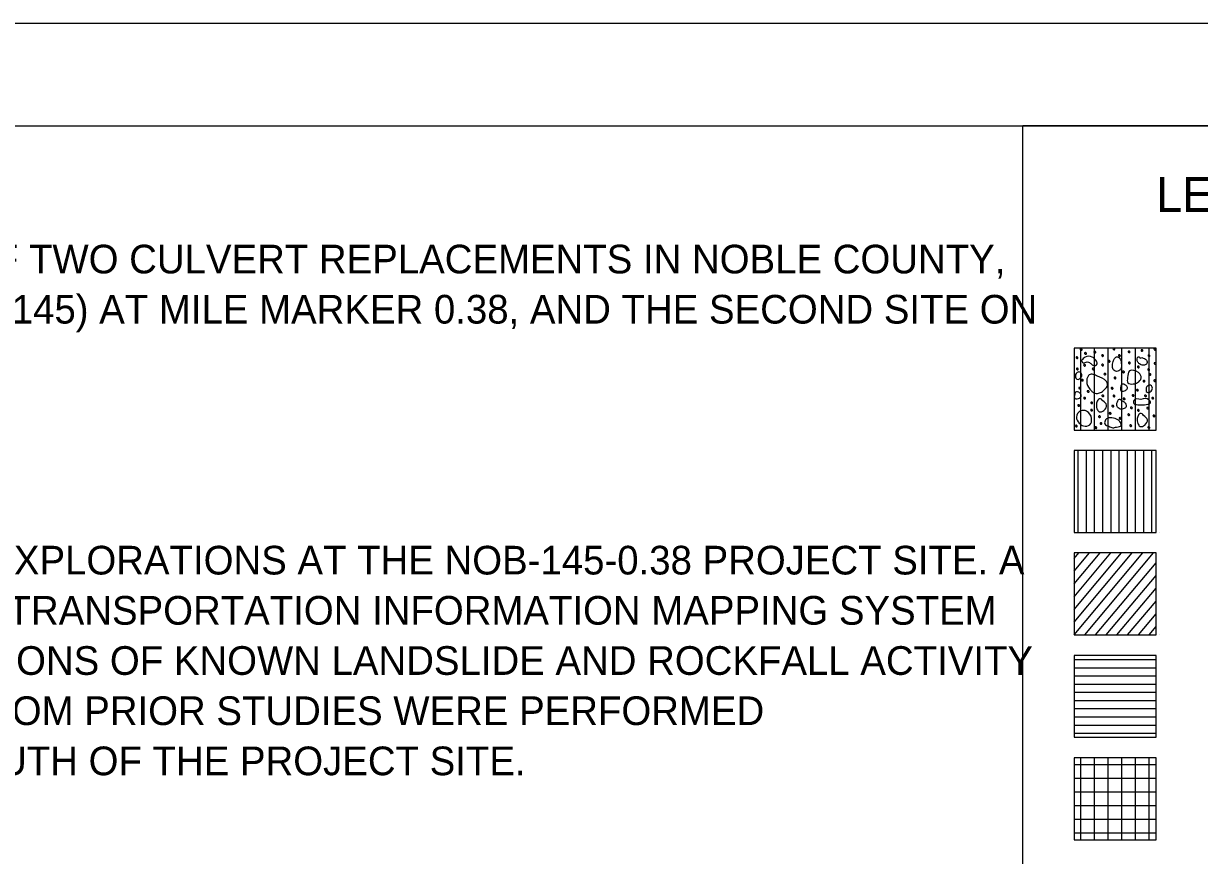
# Model space of a CAD drawing. Extents: x 0 to 34, y -8.9 to 22.
# Drawn here: x 6.83 to 12.57, y 17.94 to 22 of the extents above; entities that cross this region are included whole.
import ezdxf

# ---------------------------------------------------------------- set-up
doc = ezdxf.new("R2010")
doc.units = 0
for name, color, linetype in [('Default', 7, 'Continuous'), ('SH_Border', 7, 'Continuous'), ('SH_Cut_Line', 7, 'Continuous'), ('SH_Data', 7, 'Continuous'), ('SH_Text', 7, 'Continuous')]:
    doc.layers.add(name, color=color, linetype=linetype)

msp = doc.modelspace()

# ---------------------------------------------------------------- linework, layer by layer
at = {"layer": 'Default'}
for p, q in [((11.9545, 20.415), (11.9545, 20.415)), ((11.9878, 20.015), (11.9878, 20.415)), ((12.0545, 20.015), (12.0545, 20.415)), ((12.1212, 20.015), (12.1212, 20.415)), ((12.1878, 20.015), (12.1878, 20.415)), ((12.2545, 20.015), (12.2545, 20.415)), ((12.3212, 20.015), (12.3212, 20.415)), ((12.3545, 20.415), (12.3545, 20.415)), ((11.9545, 20.015), (11.9545, 20.015)), ((12.3545, 20.015), (12.3545, 20.015)), ((11.9545, 19.915), (11.9545, 19.915)), ((11.9745, 19.515), (11.9745, 19.915)), ((12.0145, 19.515), (12.0145, 19.915)), ((12.0545, 19.515), (12.0545, 19.915)), ((12.0945, 19.515), (12.0945, 19.915)), ((12.1345, 19.515), (12.1345, 19.915)), ((12.1745, 19.515), (12.1745, 19.915)), ((12.2145, 19.515), (12.2145, 19.915)), ((12.2545, 19.515), (12.2545, 19.915)), ((12.2945, 19.515), (12.2945, 19.915)), ((12.3345, 19.515), (12.3345, 19.915)), ((12.3545, 19.915), (12.3545, 19.915)), ((11.9545, 19.515), (11.9545, 19.515)), ((11.9545, 19.5128), (11.9545, 19.5128)), ((12.3545, 19.515), (12.3545, 19.515)), ((12.3723, 19.5128), (12.3723, 19.5128)), ((11.9544, 19.3259), (12.0292, 19.415)), ((11.9544, 19.2637), (12.0814, 19.415)), ((11.9544, 19.2015), (12.1336, 19.415)), ((11.9544, 19.1393), (12.1858, 19.415)), ((11.9544, 19.077), (12.2381, 19.415)), ((11.9545, 19.015), (12.2903, 19.415)), ((11.9545, 19.3883), (11.9769, 19.415)), ((12.0068, 19.015), (12.3425, 19.415)), ((12.059, 19.015), (12.3545, 19.3671)), ((12.1112, 19.015), (12.3545, 19.3049)), ((12.1634, 19.015), (12.3545, 19.2427)), ((12.2157, 19.015), (12.3545, 19.1805)), ((12.2679, 19.015), (12.3545, 19.1182)), ((12.3201, 19.015), (12.3545, 19.056)), ((11.9545, 19.015), (11.9545, 19.015)), ((12.3722, 19.015), (12.3722, 19.015)), ((11.9545, 18.915), (11.9545, 18.915)), ((11.9545, 18.895), (12.3545, 18.895)), ((12.3545, 18.915), (12.3545, 18.915)), ((11.9545, 18.855), (12.3545, 18.855)), ((11.9545, 18.815), (12.3545, 18.815)), ((11.9545, 18.775), (12.3545, 18.775)), ((11.9545, 18.735), (12.3545, 18.735)), ((11.9545, 18.695), (12.3545, 18.695)), ((11.9545, 18.655), (12.3545, 18.655)), ((11.9545, 18.615), (12.3545, 18.615)), ((11.9545, 18.575), (12.3545, 18.575)), ((11.9545, 18.535), (12.3545, 18.535)), ((11.9545, 18.515), (11.9545, 18.515)), ((12.3545, 18.515), (12.3545, 18.515)), ((11.9545, 18.415), (11.9545, 18.415)), ((11.9545, 18.3816), (12.3545, 18.3816)), ((11.9879, 18.015), (11.9879, 18.415)), ((12.0546, 18.015), (12.0546, 18.415)), ((12.1212, 18.015), (12.1212, 18.415)), ((12.1879, 18.015), (12.1879, 18.415)), ((12.2546, 18.015), (12.2546, 18.415)), ((12.3212, 18.015), (12.3212, 18.415)), ((12.3545, 18.415), (12.3545, 18.415)), ((11.9545, 18.315), (12.3545, 18.315)), ((11.9545, 18.2483), (12.3545, 18.2483)), ((11.9545, 18.1816), (12.3545, 18.1816)), ((11.9545, 18.115), (12.3545, 18.115)), ((11.9545, 18.0483), (12.3545, 18.0483)), ((11.9545, 18.015), (11.9545, 18.015)), ((12.3545, 18.015), (12.3545, 18.015))]:
    msp.add_line(p, q, dxfattribs=at)
for points in [[(11.9723, 20.3702), (11.9731, 20.3683), (11.9719, 20.3658), (11.9693, 20.3648), (11.9667, 20.3656), (11.9647, 20.3674), (11.9639, 20.3694), (11.9654, 20.3722), (11.9679, 20.3724), (11.9699, 20.3723), (11.9723, 20.3702)], [(11.9924, 20.4103), (11.9934, 20.4083), (11.9922, 20.4059), (11.9894, 20.4047), (11.9869, 20.4056), (11.9849, 20.4074), (11.984, 20.4094), (11.9856, 20.4122), (11.988, 20.4124), (11.99, 20.4123), (11.9924, 20.4103)], [(11.9913, 20.3546), (12.0083, 20.3716), (12.0423, 20.3716), (12.0601, 20.3562), (12.0675, 20.3383), (12.0593, 20.3302), (12.0423, 20.3343), (12.0294, 20.3448), (12.018, 20.3481), (11.9994, 20.344), (11.993, 20.3481), (11.9913, 20.3546)], [(12.0138, 20.3907), (12.0147, 20.3888), (12.0136, 20.3864), (12.0108, 20.3852), (12.0083, 20.3861), (12.0063, 20.388), (12.0054, 20.39), (12.007, 20.3927), (12.0094, 20.393), (12.0114, 20.3928), (12.0138, 20.3907)], [(12.0596, 20.3973), (12.0606, 20.3953), (12.0594, 20.3929), (12.0566, 20.3917), (12.0541, 20.3926), (12.0521, 20.3945), (12.0512, 20.3965), (12.0528, 20.3992), (12.0552, 20.3995), (12.0572, 20.3993), (12.0596, 20.3973)], [(12.0974, 20.3803), (12.0982, 20.3784), (12.097, 20.3759), (12.0944, 20.3748), (12.0918, 20.3757), (12.0898, 20.3775), (12.0889, 20.3795), (12.0905, 20.3823), (12.0929, 20.3825), (12.0949, 20.3824), (12.0974, 20.3803)], [(12.147, 20.3553), (12.1412, 20.3302), (12.1458, 20.3107), (12.1618, 20.3015), (12.1813, 20.3107), (12.1847, 20.3416), (12.1767, 20.3657), (12.1618, 20.3726), (12.1492, 20.3611), (12.147, 20.3553)], [(12.1526, 20.4124), (12.1534, 20.4105), (12.1523, 20.4081), (12.1496, 20.407), (12.147, 20.4078), (12.145, 20.4097), (12.1442, 20.4117), (12.1457, 20.4144), (12.1482, 20.4147), (12.1502, 20.4146), (12.1526, 20.4124)], [(12.1795, 20.3799), (12.1805, 20.378), (12.1793, 20.3756), (12.1765, 20.3744), (12.174, 20.3753), (12.172, 20.3772), (12.1711, 20.3792), (12.1727, 20.3819), (12.1751, 20.3822), (12.1771, 20.382), (12.1795, 20.3799)], [(12.2265, 20.3985), (12.2274, 20.3965), (12.2263, 20.3941), (12.2235, 20.393), (12.221, 20.3939), (12.219, 20.3957), (12.2181, 20.3977), (12.2196, 20.4005), (12.2221, 20.4007), (12.2241, 20.4005), (12.2265, 20.3985)], [(12.2632, 20.3687), (12.2638, 20.3492), (12.274, 20.3377), (12.2912, 20.332), (12.305, 20.3348), (12.3107, 20.3486), (12.3027, 20.3612), (12.2912, 20.3669), (12.2844, 20.3687), (12.278, 20.3663), (12.273, 20.3715), (12.2666, 20.3721), (12.2632, 20.3687)], [(12.2894, 20.4047), (12.2902, 20.4029), (12.289, 20.4005), (12.2864, 20.3993), (12.2838, 20.4001), (12.2818, 20.402), (12.2809, 20.404), (12.2824, 20.4067), (12.2849, 20.407), (12.2869, 20.4069), (12.2894, 20.4047)], [(12.3237, 20.3799), (12.3245, 20.378), (12.3235, 20.3756), (12.3207, 20.3744), (12.3181, 20.3753), (12.3161, 20.3772), (12.3153, 20.3792), (12.3169, 20.3819), (12.3193, 20.3822), (12.3213, 20.382), (12.3237, 20.3799)], [(12.3527, 20.4104), (12.3536, 20.4085), (12.3524, 20.4061), (12.3497, 20.405), (12.3471, 20.4058), (12.3451, 20.4077), (12.3443, 20.4097), (12.3458, 20.4124), (12.3483, 20.4127), (12.3503, 20.4125), (12.3527, 20.4104)], [(11.9739, 20.3151), (11.9747, 20.3132), (11.9736, 20.3107), (11.9709, 20.3096), (11.9683, 20.3105), (11.9663, 20.3123), (11.9655, 20.3143), (11.967, 20.3171), (11.9695, 20.3173), (11.9715, 20.3172), (11.9739, 20.3151)], [(12.0094, 20.333), (12.0104, 20.331), (12.0092, 20.3286), (12.0065, 20.3274), (12.004, 20.3283), (12.002, 20.3302), (12.001, 20.3322), (12.0026, 20.3349), (12.005, 20.3352), (12.0071, 20.335), (12.0094, 20.333)], [(12.0516, 20.3151), (12.0525, 20.3132), (12.0514, 20.3107), (12.0486, 20.3096), (12.046, 20.3105), (12.044, 20.3123), (12.0432, 20.3143), (12.0448, 20.3171), (12.0472, 20.3173), (12.0492, 20.3172), (12.0516, 20.3151)], [(12.0973, 20.334), (12.0981, 20.3322), (12.097, 20.3297), (12.0943, 20.3286), (12.0917, 20.3294), (12.0897, 20.3313), (12.0888, 20.3333), (12.0904, 20.336), (12.0928, 20.3363), (12.0949, 20.3362), (12.0973, 20.334)], [(12.1294, 20.3523), (12.1302, 20.3505), (12.129, 20.348), (12.1264, 20.3469), (12.1238, 20.3477), (12.1218, 20.3496), (12.1209, 20.3516), (12.1225, 20.3543), (12.125, 20.3546), (12.127, 20.3545), (12.1294, 20.3523)], [(12.2281, 20.3442), (12.229, 20.3423), (12.2279, 20.3399), (12.2251, 20.3388), (12.2225, 20.3397), (12.2205, 20.3415), (12.2197, 20.3435), (12.2213, 20.3462), (12.2237, 20.3465), (12.2257, 20.3464), (12.2281, 20.3442)], [(12.2719, 20.3247), (12.2727, 20.3229), (12.2716, 20.3205), (12.2689, 20.3193), (12.2663, 20.3202), (12.2643, 20.3221), (12.2635, 20.3241), (12.265, 20.3268), (12.2675, 20.3271), (12.2695, 20.3269), (12.2719, 20.3247)], [(12.3221, 20.3118), (12.323, 20.3099), (12.3218, 20.3075), (12.319, 20.3064), (12.3165, 20.3072), (12.3145, 20.3091), (12.3136, 20.3111), (12.3152, 20.3138), (12.3176, 20.3141), (12.3196, 20.314), (12.3221, 20.3118)], [(12.3535, 20.3419), (12.3543, 20.3401), (12.3531, 20.3376), (12.3505, 20.3365), (12.3479, 20.3373), (12.3459, 20.3391), (12.345, 20.3411), (12.3466, 20.3439), (12.349, 20.3441), (12.3511, 20.3441), (12.3535, 20.3419)], [(11.97, 20.2957), (11.978, 20.2997), (11.9878, 20.2951), (11.9924, 20.2842), (11.989, 20.2738), (11.9815, 20.2658), (11.9735, 20.2624), (11.9626, 20.2688), (11.9615, 20.2784), (11.962, 20.2865), (11.97, 20.2957)], [(11.9982, 20.2604), (11.999, 20.2586), (11.9979, 20.2561), (11.9952, 20.255), (11.9926, 20.2558), (11.9906, 20.2577), (11.9897, 20.2597), (11.9913, 20.2624), (11.9938, 20.2627), (11.9958, 20.2626), (11.9982, 20.2604)], [(12.0386, 20.2065), (12.0169, 20.2432), (12.0192, 20.2718), (12.0284, 20.2845), (12.0478, 20.2867), (12.0685, 20.2776), (12.112, 20.2523), (12.1165, 20.2283), (12.1085, 20.2192), (12.0925, 20.2031), (12.0741, 20.1951), (12.0627, 20.1939), (12.0501, 20.1973), (12.0386, 20.2065)], [(12.1085, 20.2893), (12.1094, 20.2875), (12.1082, 20.2851), (12.1055, 20.2839), (12.1029, 20.2847), (12.1009, 20.2867), (12.1, 20.2887), (12.1016, 20.2913), (12.104, 20.2917), (12.106, 20.2915), (12.1085, 20.2893)], [(12.158, 20.2712), (12.159, 20.2692), (12.158, 20.2668), (12.1552, 20.2657), (12.1526, 20.2665), (12.1506, 20.2684), (12.1498, 20.2704), (12.1514, 20.2731), (12.1538, 20.2734), (12.1558, 20.2733), (12.158, 20.2712)], [(12.199, 20.3005), (12.1999, 20.2986), (12.1987, 20.2962), (12.196, 20.295), (12.1935, 20.2959), (12.1914, 20.2978), (12.1905, 20.2997), (12.1921, 20.3025), (12.1945, 20.3027), (12.1965, 20.3026), (12.199, 20.3005)], [(12.2153, 20.2711), (12.225, 20.3035), (12.2687, 20.2954), (12.2816, 20.2695), (12.2639, 20.2467), (12.2428, 20.2403), (12.2169, 20.2452), (12.2153, 20.2711)], [(12.2995, 20.2551), (12.3003, 20.2532), (12.2991, 20.2508), (12.2964, 20.2497), (12.2938, 20.2505), (12.2918, 20.2523), (12.291, 20.2543), (12.2925, 20.2571), (12.295, 20.2574), (12.297, 20.2572), (12.2995, 20.2551)], [(12.3285, 20.2875), (12.3295, 20.2857), (12.3283, 20.2832), (12.3255, 20.2821), (12.323, 20.2829), (12.321, 20.2847), (12.3201, 20.2867), (12.3217, 20.2895), (12.3241, 20.2898), (12.3261, 20.2897), (12.3285, 20.2875)], [(12.352, 20.2574), (12.353, 20.2556), (12.3518, 20.2531), (12.349, 20.252), (12.3465, 20.2528), (12.3445, 20.2546), (12.3436, 20.2566), (12.3452, 20.2594), (12.3476, 20.2597), (12.3496, 20.2596), (12.352, 20.2574)], [(11.957, 20.1852), (11.961, 20.1998), (11.9829, 20.1958), (11.9893, 20.1828), (11.9804, 20.1715), (11.9699, 20.1683), (11.957, 20.1707), (11.957, 20.1852)], [(11.9858, 20.2213), (11.9867, 20.2194), (11.9855, 20.217), (11.9828, 20.2159), (11.9802, 20.2167), (11.9782, 20.2186), (11.9774, 20.2206), (11.979, 20.2233), (11.9814, 20.2236), (11.9834, 20.2235), (11.9858, 20.2213)], [(12.0269, 20.2052), (12.0279, 20.2033), (12.0267, 20.2008), (12.024, 20.1997), (12.0215, 20.2005), (12.0195, 20.2024), (12.0186, 20.2044), (12.0201, 20.2071), (12.0226, 20.2074), (12.0246, 20.2072), (12.0269, 20.2052)], [(12.144, 20.2203), (12.1448, 20.2185), (12.1436, 20.2161), (12.141, 20.2149), (12.1384, 20.2157), (12.1364, 20.2177), (12.1355, 20.2197), (12.137, 20.2223), (12.1395, 20.2227), (12.1415, 20.2225), (12.144, 20.2203)], [(12.1816, 20.2208), (12.1865, 20.2371), (12.2083, 20.233), (12.2148, 20.22), (12.2059, 20.2087), (12.1954, 20.2054), (12.1824, 20.2079), (12.1816, 20.2208)], [(12.267, 20.2113), (12.2679, 20.2095), (12.2667, 20.207), (12.264, 20.2059), (12.2615, 20.2067), (12.2595, 20.2086), (12.2585, 20.2106), (12.2601, 20.2133), (12.2626, 20.2136), (12.2646, 20.2135), (12.267, 20.2113)], [(12.3149, 20.2316), (12.3224, 20.235), (12.332, 20.2304), (12.3366, 20.2195), (12.3332, 20.2092), (12.3258, 20.2012), (12.3178, 20.1977), (12.3069, 20.2041), (12.3057, 20.2138), (12.3063, 20.2218), (12.3149, 20.2316)], [(12.0094, 20.1726), (12.0104, 20.1706), (12.0092, 20.1682), (12.0065, 20.167), (12.004, 20.1678), (12.002, 20.1698), (12.001, 20.1717), (12.0026, 20.1744), (12.005, 20.1747), (12.0071, 20.1746), (12.0094, 20.1726)], [(12.0437, 20.1496), (12.0447, 20.1476), (12.0435, 20.1452), (12.0408, 20.144), (12.0382, 20.1449), (12.0362, 20.1468), (12.0354, 20.1487), (12.037, 20.1515), (12.0394, 20.1517), (12.0414, 20.1516), (12.0437, 20.1496)], [(12.0945, 20.1571), (12.1131, 20.1368), (12.1001, 20.1109), (12.0775, 20.1044), (12.0661, 20.119), (12.0637, 20.1425), (12.0702, 20.1603), (12.0783, 20.1668), (12.088, 20.1652), (12.0945, 20.1571)], [(12.0986, 20.1837), (12.0995, 20.1819), (12.0983, 20.1795), (12.0956, 20.1783), (12.093, 20.1792), (12.091, 20.1811), (12.0901, 20.1831), (12.0917, 20.1857), (12.0941, 20.1861), (12.0961, 20.1859), (12.0986, 20.1837)], [(12.153, 20.1827), (12.1538, 20.1809), (12.1526, 20.1785), (12.15, 20.1773), (12.1474, 20.1782), (12.1454, 20.1801), (12.1445, 20.1821), (12.146, 20.1848), (12.1485, 20.1851), (12.1505, 20.1849), (12.153, 20.1827)], [(12.1719, 20.1649), (12.163, 20.139), (12.1695, 20.1236), (12.18, 20.1179), (12.1986, 20.1203), (12.2083, 20.1292), (12.2067, 20.1423), (12.1945, 20.156), (12.184, 20.1617), (12.1784, 20.1657), (12.1719, 20.1649)], [(12.2022, 20.1692), (12.2031, 20.1673), (12.202, 20.1649), (12.1992, 20.1638), (12.1966, 20.1646), (12.1946, 20.1665), (12.1938, 20.1685), (12.1954, 20.1712), (12.1978, 20.1715), (12.1998, 20.1713), (12.2022, 20.1692)], [(12.246, 20.1854), (12.2468, 20.1835), (12.2457, 20.1811), (12.243, 20.1799), (12.2404, 20.1808), (12.2384, 20.1827), (12.2375, 20.1847), (12.2391, 20.1874), (12.2415, 20.1877), (12.2435, 20.1875), (12.246, 20.1854)], [(12.2805, 20.1648), (12.3195, 20.1625), (12.3275, 20.1487), (12.3138, 20.1408), (12.2851, 20.1384), (12.2588, 20.1396), (12.244, 20.1476), (12.2462, 20.1602), (12.2805, 20.1648)], [(12.3062, 20.1839), (12.3073, 20.1819), (12.3061, 20.1795), (12.3034, 20.1783), (12.3008, 20.1792), (12.2988, 20.1811), (12.298, 20.1831), (12.2995, 20.1857), (12.302, 20.1861), (12.304, 20.1859), (12.3062, 20.1839)], [(12.342, 20.1724), (12.3428, 20.1706), (12.3417, 20.1682), (12.339, 20.167), (12.3364, 20.1678), (12.3344, 20.1698), (12.3335, 20.1717), (12.3351, 20.1744), (12.3376, 20.1747), (12.3396, 20.1746), (12.342, 20.1724)], [(11.9791, 20.0492), (11.9654, 20.0778), (11.9871, 20.1088), (12.0146, 20.1076), (12.0398, 20.0709), (12.0306, 20.0412), (11.9997, 20.0354), (11.9791, 20.0492)], [(11.9802, 20.1369), (11.9812, 20.1349), (11.98, 20.1325), (11.9774, 20.1313), (11.9748, 20.1322), (11.9728, 20.1341), (11.972, 20.1361), (11.9735, 20.1387), (11.976, 20.1391), (11.978, 20.1389), (11.9802, 20.1369)], [(12.0434, 20.1138), (12.0444, 20.1118), (12.0432, 20.1093), (12.0405, 20.1082), (12.038, 20.1091), (12.036, 20.1109), (12.035, 20.1129), (12.0366, 20.1157), (12.0391, 20.1159), (12.0411, 20.1158), (12.0434, 20.1138)], [(12.0823, 20.0818), (12.0833, 20.0798), (12.0821, 20.0773), (12.0794, 20.0762), (12.0768, 20.0771), (12.0748, 20.0789), (12.074, 20.0809), (12.0755, 20.0837), (12.078, 20.0839), (12.08, 20.0838), (12.0823, 20.0818)], [(12.1342, 20.0978), (12.135, 20.096), (12.134, 20.0936), (12.1312, 20.0924), (12.1286, 20.0933), (12.1266, 20.0952), (12.1258, 20.0972), (12.1274, 20.0999), (12.1298, 20.1002), (12.1318, 20.1), (12.1342, 20.0978)], [(12.1472, 20.1335), (12.148, 20.1317), (12.1469, 20.1292), (12.1442, 20.1281), (12.1416, 20.1289), (12.1396, 20.1308), (12.1387, 20.1328), (12.1403, 20.1355), (12.1427, 20.1358), (12.1447, 20.1357), (12.1472, 20.1335)], [(12.225, 20.0914), (12.2258, 20.0895), (12.2246, 20.0871), (12.2219, 20.0859), (12.2193, 20.0868), (12.2173, 20.0887), (12.2165, 20.0907), (12.218, 20.0934), (12.2205, 20.0937), (12.2225, 20.0935), (12.225, 20.0914)], [(12.2379, 20.1254), (12.2387, 20.1236), (12.2376, 20.1212), (12.2349, 20.12), (12.2323, 20.1208), (12.2303, 20.1227), (12.2295, 20.1247), (12.231, 20.1274), (12.2335, 20.1277), (12.2355, 20.1276), (12.2379, 20.1254)], [(12.2933, 20.0867), (12.3119, 20.0657), (12.299, 20.0397), (12.2763, 20.0333), (12.265, 20.0479), (12.2625, 20.0714), (12.269, 20.0892), (12.2771, 20.0957), (12.2868, 20.0941), (12.2933, 20.0867)], [(12.2718, 20.1127), (12.2727, 20.1109), (12.2715, 20.1085), (12.2688, 20.1073), (12.2663, 20.1081), (12.2643, 20.11), (12.2633, 20.112), (12.2649, 20.1147), (12.2673, 20.1151), (12.2693, 20.1149), (12.2718, 20.1127)], [(12.3177, 20.1238), (12.3186, 20.1219), (12.3174, 20.1195), (12.3147, 20.1183), (12.3121, 20.1193), (12.3101, 20.1211), (12.3092, 20.1231), (12.3108, 20.1258), (12.3132, 20.1261), (12.3152, 20.1259), (12.3177, 20.1238)], [(12.3477, 20.0857), (12.3486, 20.0837), (12.3474, 20.0813), (12.3447, 20.0802), (12.3422, 20.0811), (12.3402, 20.0829), (12.3392, 20.0849), (12.3408, 20.0877), (12.3432, 20.0879), (12.3452, 20.0877), (12.3477, 20.0857)], [(11.969, 20.0362), (11.9699, 20.0344), (11.9687, 20.032), (11.966, 20.0308), (11.9635, 20.0317), (11.9615, 20.0336), (11.9605, 20.0356), (11.9621, 20.0382), (11.9646, 20.0386), (11.9666, 20.0384), (11.969, 20.0362)], [(12.0645, 20.0282), (12.0655, 20.0263), (12.0643, 20.0239), (12.0615, 20.0227), (12.059, 20.0237), (12.057, 20.0255), (12.0561, 20.0275), (12.0577, 20.0302), (12.0601, 20.0305), (12.0621, 20.0303), (12.0645, 20.0282)], [(12.0895, 20.0486), (12.0905, 20.0466), (12.0894, 20.0442), (12.0867, 20.043), (12.0841, 20.0438), (12.0821, 20.0457), (12.0812, 20.0478), (12.0828, 20.0504), (12.0853, 20.0508), (12.0873, 20.0506), (12.0895, 20.0486)], [(12.1241, 20.0337), (12.1047, 20.045), (12.1079, 20.0652), (12.1298, 20.075), (12.1621, 20.0685), (12.1808, 20.0523), (12.184, 20.0369), (12.1621, 20.0296), (12.1435, 20.0263), (12.1241, 20.0337)], [(12.1827, 20.0737), (12.1837, 20.0717), (12.1825, 20.0693), (12.1798, 20.0681), (12.1772, 20.069), (12.1752, 20.0708), (12.1744, 20.0728), (12.176, 20.0756), (12.1784, 20.0758), (12.1804, 20.0757), (12.1827, 20.0737)], [(12.2346, 20.0379), (12.2355, 20.036), (12.2344, 20.0336), (12.2316, 20.0325), (12.229, 20.0333), (12.227, 20.0352), (12.2262, 20.0372), (12.2278, 20.0399), (12.2302, 20.0402), (12.2322, 20.0401), (12.2346, 20.0379)], [(12.3228, 20.0292), (12.3238, 20.0271), (12.3226, 20.0247), (12.3199, 20.0236), (12.3174, 20.0244), (12.3153, 20.0263), (12.3145, 20.0282), (12.316, 20.031), (12.3185, 20.0312), (12.3205, 20.0312), (12.3228, 20.0292)]]:
    msp.add_spline(points, degree=3, dxfattribs=at)
at = {"layer": 'SH_Border'}
msp.add_lwpolyline([(1.5, 21.5), (33.5, 21.5), (33.5, 0.5), (1.5, 0.5)], close=True, dxfattribs=at)
at = {"layer": 'SH_Cut_Line'}
msp.add_lwpolyline([(0, 0), (34, 0), (34, 22), (0, 22)], close=True, dxfattribs=at)
at = {"layer": 'SH_Data'}
for p in [(11.7045, 1.1573), (21.8712, 21.5)]:
    msp.add_line(p, (11.7045, 21.5), dxfattribs=at)
for points in [[(11.9545, 20.015), (12.3545, 20.015), (12.3545, 20.415), (11.9545, 20.415)], [(11.9545, 19.515), (12.3545, 19.515), (12.3545, 19.915), (11.9545, 19.915)], [(11.9545, 19.015), (12.3545, 19.015), (12.3545, 19.415), (11.9545, 19.415)], [(11.9545, 18.515), (12.3545, 18.515), (12.3545, 18.915), (11.9545, 18.915)], [(11.9545, 18.015), (12.3545, 18.015), (12.3545, 18.415), (11.9545, 18.415)]]:
    msp.add_lwpolyline(points, close=True, dxfattribs=at)

# ---------------------------------------------------------------- texts
at = {"layer": 'SH_Text'}
for s, height, p in [('LEGEND', 0.17, (12.3555, 21.08)), ('THE NOB-145/147-0.38/18.42 PROJECT CONSISTS OF TWO CULVERT REPLACEMENTS IN NOBLE COUNTY, ', 0.14, (2.0379, 20.78)), ('OHIO. THE FIRST SITE IS ON STATE ROUTE 145 (SR 145) AT MILE MARKER 0.38, AND THE SECOND SITE ON ', 0.14, (2.0379, 20.535)), ('HDR IS UNAWARE OF ANY PRIOR GEOTECHNICAL EXPLORATIONS AT THE NOB-145-0.38 PROJECT SITE. A ', 0.14, (2.0379, 19.31)), ('SEARCH OF THE AVAILABLE RECORDS ON ODOT’S TRANSPORTATION INFORMATION MAPPING SYSTEM ', 0.14, (2.0379, 19.065)), ('(TIMS) REVEALS ONLY THE GEOGRAPHICAL LOCATIONS OF KNOWN LANDSLIDE AND ROCKFALL ACTIVITY ', 0.14, (2.0379, 18.82)), ('IN THE PROJECT AREA. THE NEAREST BORINGS FROM PRIOR STUDIES WERE PERFORMED ', 0.14, (2.0379, 18.575)), ('APPROXIMATELY 0.2 MILE NORTH AND 0.4 MILE SOUTH OF THE PROJECT SITE.', 0.14, (2.0379, 18.33))]:
    msp.add_text(s, height=height, dxfattribs=at).set_placement(p)

doc.saveas('drawing.dxf')
